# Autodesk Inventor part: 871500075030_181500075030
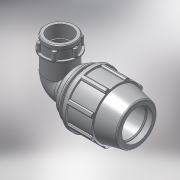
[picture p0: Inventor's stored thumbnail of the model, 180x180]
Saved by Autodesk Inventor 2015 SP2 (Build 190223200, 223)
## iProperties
Created: 2017-02
Part Number: 871500075030_181500075030
Material: PVC-Piping
Description: PLASSON 90° ELBOW FEMALE ADAPTOR 75-3"
Document SubType Name: Modeling
Designer: KIM
Mass: 92.6774 g
Surface Area: 199.44 cm^2
Volume: 66.1981 cm^3
Density: 1.4 g/cm^3
Appearance: Smooth - White
Author: KIM
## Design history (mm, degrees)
derived "87150.ipt"
feature "Solid1::87150.ipt"
tag "TaggingFeature1"
body "Solid1"
other parameters: "d2" = 75, "d4" = 16.33333, "d5" = 49, "d7" = 132, "d9" = 28, "d11" = 4.9, "d13" = 120 deg, "d14" = 97.5, "d15" = 12 deg, "d16" = 125.4, "d18" = 3.75, "d19" = 35 deg, "d20" = 17.5 deg, "d21" = 122.76, "d23" = 0, "d25" = 360 deg, "d27" = 2.64, "d33" = 1.5, "d42" = 72.52, "d43" = 3.96, "d46" = 2.25, "d51" = 196, "d68" = 9.8, "d72" = 105, "d73" = 110.4038, "d74" = 36, "d75" = 126.96437, "d76" = 84.926, "d77" = 39.6, "d79" = 33.9704, "d80" = 2.54778, "d83" = 0, "d84" = 0, "d91" = 118.8, "d93" = 137, "d94" = 84.926, "d95" = 59.4482, "d96" = 9.8, "d97" = 50 deg, "d98" = 76.4334, "d99" = 0.5, "d100" = 0.5, "d101" = 12, "d102" = 110.4038, "d103" = 30.24, "d104" = 0, "d108" = 360 deg, "d110" = 2.3658, "d111" = 8.8, "d112" = 0, "d113" = 2.45, "d114" = 2.45, "d115" = 121.638, "d_" = 75, "E_" = 132, "A_" = 196, "l_" = 137, "l_2" = 36, "A_1" = 105, "Rp_" = 84.926, "d105" = 16.56057
